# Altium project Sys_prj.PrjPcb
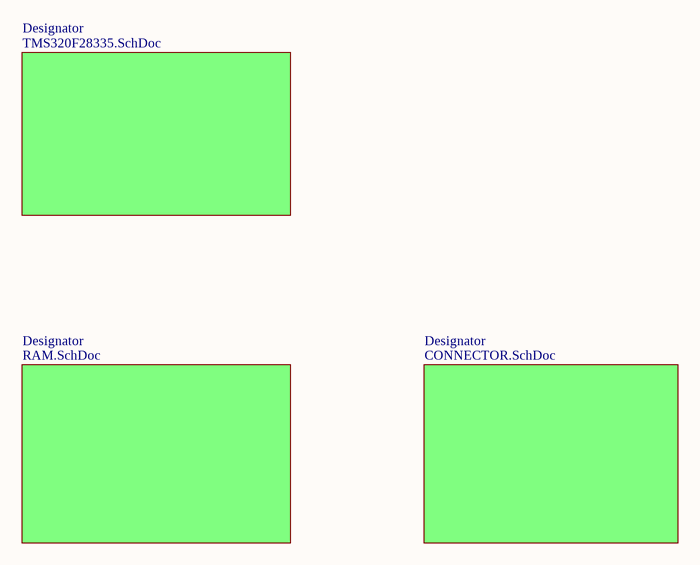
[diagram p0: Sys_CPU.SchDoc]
4 sheets, 71 parts. Net scope: global (net labels, ports and power ports of the same name join across sheets).
Board file: Sys_CPU.PcbDoc
Sheets:
  Sys_CPU.SchDoc
    Designator = TMS320F28335.SchDoc
    Designator = RAM.SchDoc
    Designator = CONNECTOR.SchDoc

## Sheet Sys_CPU.SchDoc
size A4

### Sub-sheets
Designator = TMS320F28335.SchDoc: no entries
Designator = RAM.SchDoc: no entries
Designator = CONNECTOR.SchDoc: no entries

## Sheet TMS320F28335.SchDoc
size A3
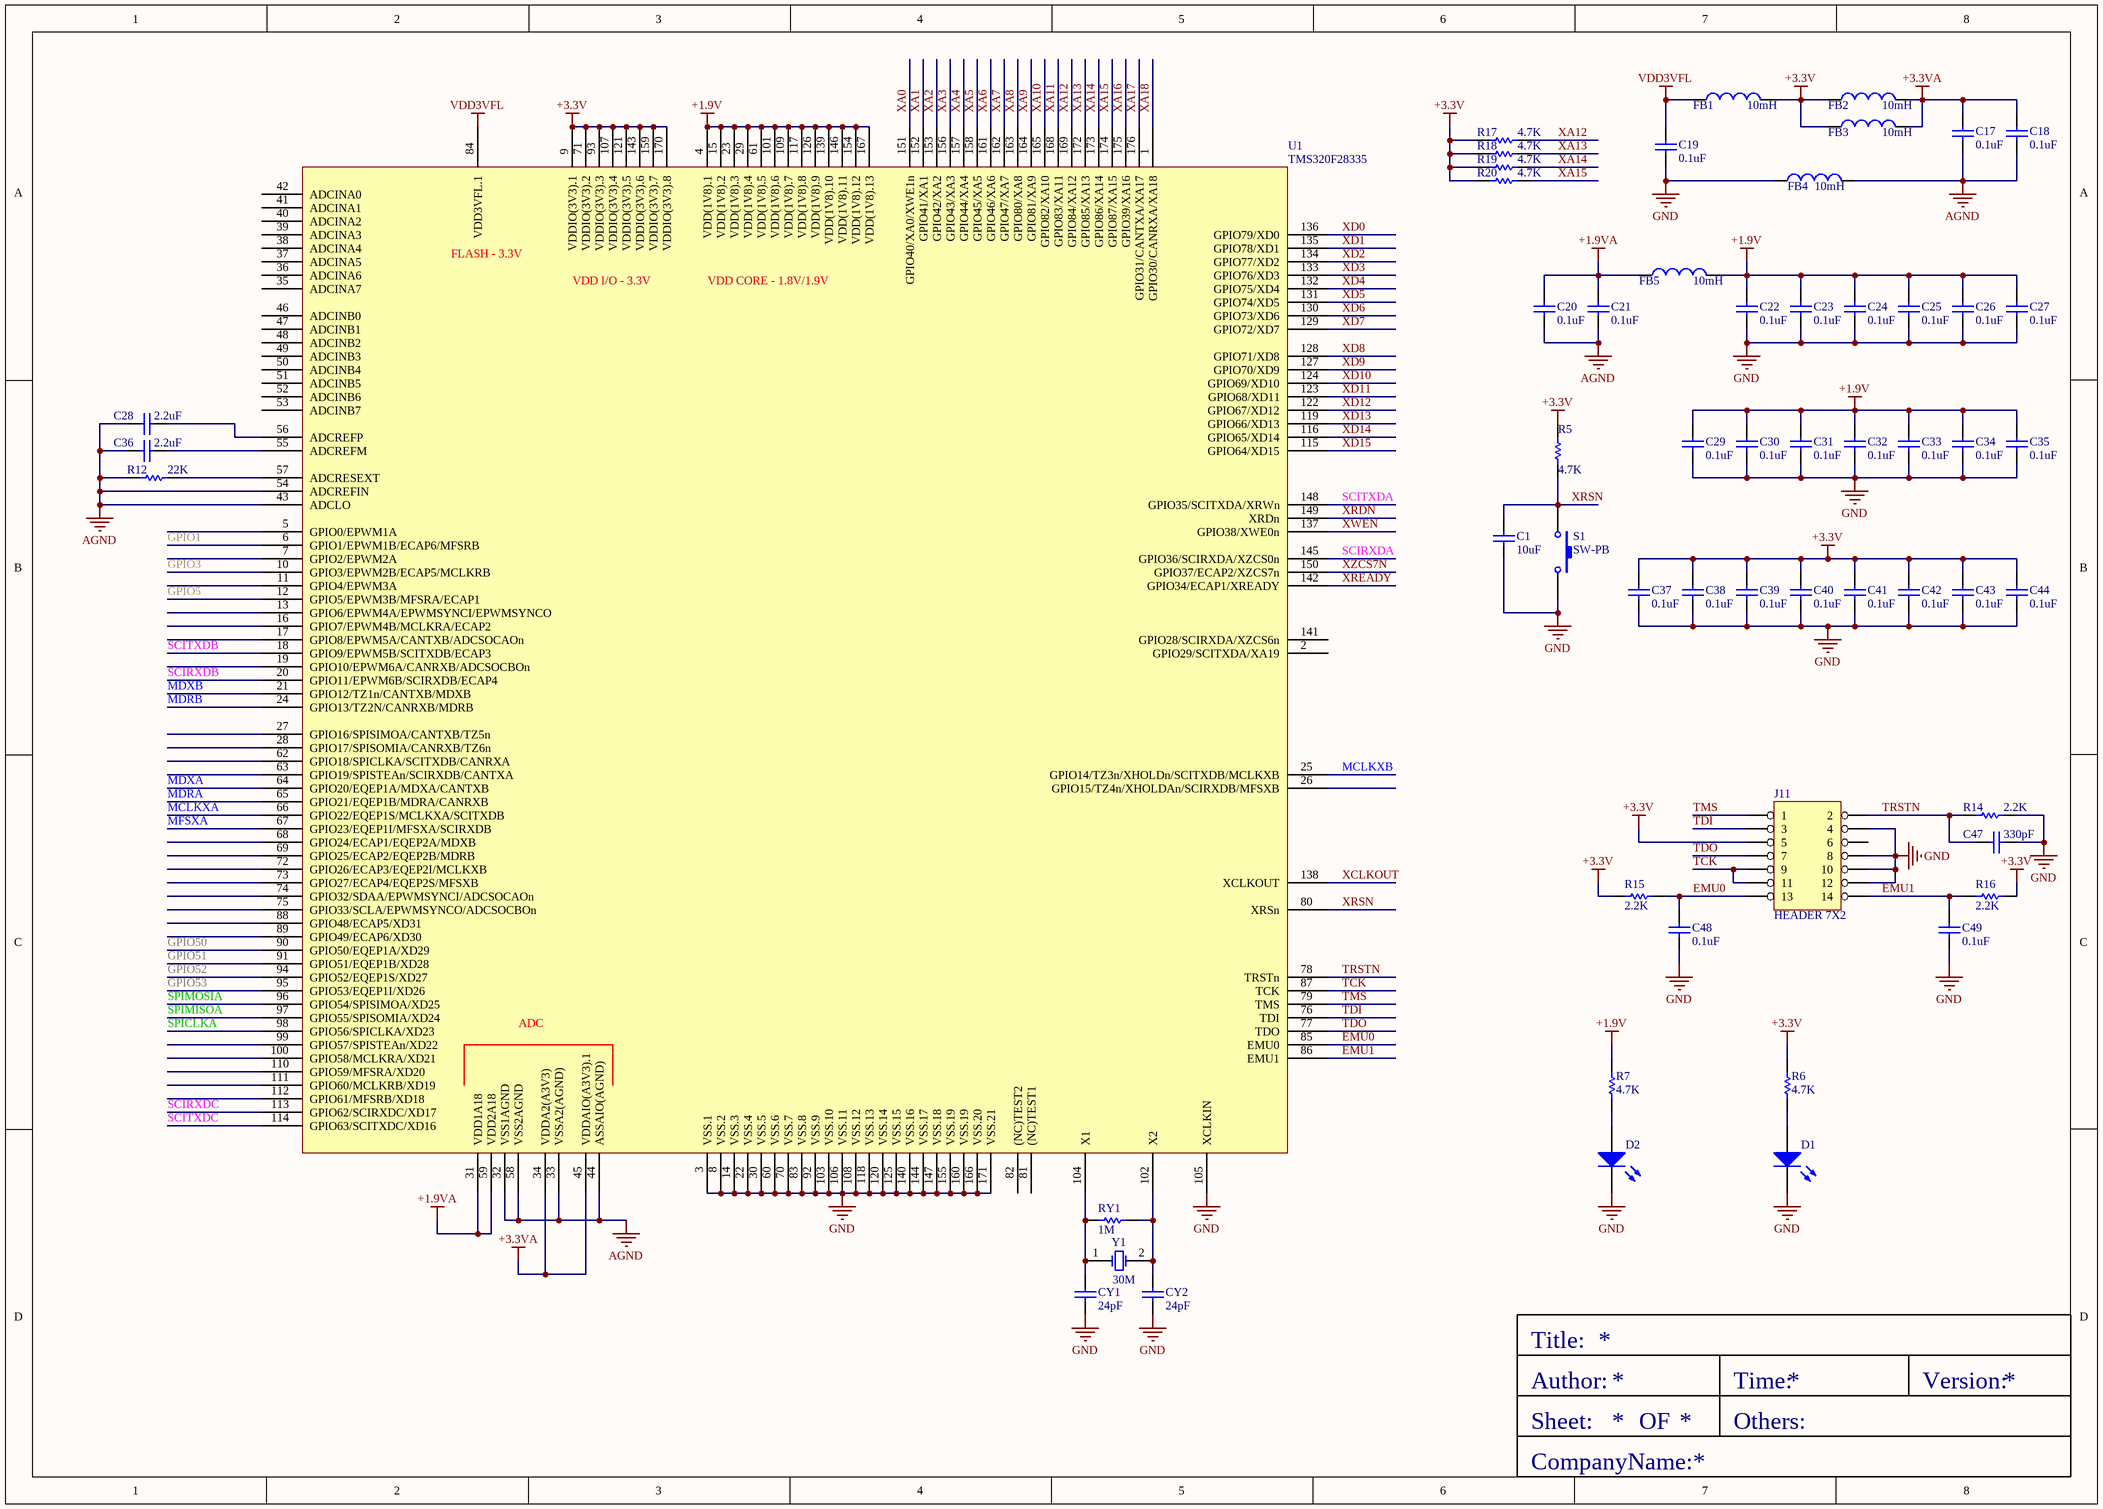
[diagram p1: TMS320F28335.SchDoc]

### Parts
C1  value 10uF  [6-0805_L]  (hidden comment: Cap)
C17  0.1uF  [1608[0603]]
C18  0.1uF  [1608[0603]]
C19  0.1uF  [1608[0603]]
C20  0.1uF  [1608[0603]]
C21  0.1uF  [1608[0603]]
C22  0.1uF  [1608[0603]]
C23  0.1uF  [1608[0603]]
C24  0.1uF  [1608[0603]]
C25  0.1uF  [1608[0603]]
C26  0.1uF  [1608[0603]]
C27  0.1uF  [1608[0603]]
C28  value 2.2uF  [6-0805_L]  (hidden comment: Cap)
C29  0.1uF  [1608[0603]]
C30  0.1uF  [1608[0603]]
C31  0.1uF  [1608[0603]]
C32  0.1uF  [1608[0603]]
C33  0.1uF  [1608[0603]]
C34  0.1uF  [1608[0603]]
C35  0.1uF  [1608[0603]]
C36  value 2.2uF  [6-0805_L]  (hidden comment: Cap)
C37  0.1uF  [1608[0603]]
C38  0.1uF  [1608[0603]]
C39  0.1uF  [1608[0603]]
C40  0.1uF  [1608[0603]]
C41  0.1uF  [1608[0603]]
C42  0.1uF  [1608[0603]]
C43  0.1uF  [1608[0603]]
C44  0.1uF  [1608[0603]]
C47  330pF  [1608[0603]]
C48  0.1uF  [1608[0603]]
C49  0.1uF  [1608[0603]]
CY1  value 24pF  [0603]  (hidden comment: Cap)
CY2  value 24pF  [0603]  (hidden comment: Cap)
D1  LED3  [SMD _LED]  (value not drawn)
D2  LED3  [SMD _LED]  (value not drawn)
FB1  value 10mH  [C1206]  (hidden comment: Inductor)
FB2  value 10mH  [C1206]  (hidden comment: Inductor)
FB3  value 10mH  [C1206]  (hidden comment: Inductor)
FB4  value 10mH  [C1206]  (hidden comment: Inductor)
FB5  value 10mH  [C1206]  (hidden comment: Inductor)
J11  HEADER 7X2  [IDC-14]
R5  value 4.7K  [1608[0603]]  (hidden comment: Res1)
R6  value 4.7K  [1608[0603]]  (hidden comment: Res1)
R7  value 4.7K  [1608[0603]]  (hidden comment: Res1)
R12  value 22K  [1608[0603]]  (hidden comment: Res1)
R14  2.2K  [1608[0603]]
R15  2.2K  [1608[0603]]
R16  2.2K  [1608[0603]]
R17  value 4.7K  [1608[0603]]  (hidden comment: Res1)
R18  value 4.7K  [1608[0603]]  (hidden comment: Res1)
R19  value 4.7K  [1608[0603]]  (hidden comment: Res1)
R20  value 4.7K  [1608[0603]]  (hidden comment: Res1)
RY1  value 1M  [0603]  (hidden comment: Res1)
S1  SW-PB  [3*6*2.5]
U1  TMS320F28335  [PQFP-176]
Y1  value 30M  [SMD-CRYSTAL-2POLE]  (hidden comment: XTAL)

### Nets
+1.9V: C22.2 C23.2 C24.2 C25.2 C26.2 C27.2 C29.2 C30.2 C31.2 C32.2 C33.2 C34.2 C35.2 FB5.2 R7.2 U1.4(VDD(1V8).1) U1.15(VDD(1V8).2) U1.23(VDD(1V8).3) U1.29(VDD(1V8).4) U1.61(VDD(1V8).5) U1.101(VDD(1V8).6) U1.109(VDD(1V8).7) U1.117(VDD(1V8).8) U1.126(VDD(1V8).9) U1.139(VDD(1V8).10) U1.146(VDD(1V8).11) U1.154(VDD(1V8).12) U1.167(VDD(1V8).13)
+1.9VA: C20.2 C21.2 FB5.1 U1.31(VDD1A18) U1.59(VDD2A18)
+3.3V: C37.2 C38.2 C39.2 C40.2 C41.2 C42.2 C43.2 C44.2 FB1.2 FB2.1 FB3.1 J11.5 R5.2 R6.2 R15.1 R16.2 R17.1 R18.1 R19.1 R20.1 U1.9(VDDIO(3V3).1) U1.71(VDDIO(3V3).2) U1.93(VDDIO(3V3).3) U1.107(VDDIO(3V3).4) U1.121(VDDIO(3V3).5) U1.143(VDDIO(3V3).6) U1.159(VDDIO(3V3).7) U1.170(VDDIO(3V3).8)
+3.3VA: C17.2 C18.2 FB2.2 FB3.2 U1.34(VDDA2(A3V3)) U1.45(VDDAIO(A3V3).1)
AGND: C17.1 C18.1 C20.1 C21.1 C28.1 C36.1 FB4.2 R12.1 U1.32(VSS1AGND) U1.33(VSSA2(AGND)) U1.43(ADCLO) U1.44(ASSAIO(AGND)) U1.54(ADCREFIN) U1.58(VSS2AGND)
GND: C1.1 C19.1 C22.1 C23.1 C24.1 C25.1 C26.1 C27.1 C29.1 C30.1 C31.1 C32.1 C33.1 C34.1 C35.1 C37.1 C38.1 C39.1 C40.1 C41.1 C42.1 C43.1 C44.1 C47.1 C48.1 C49.1 CY1.1 CY2.1 D1.2(K) D2.2(K) FB4.1 J11.4 J11.8 J11.10 J11.12 R14.2 S1.2 U1.3(VSS.1) U1.8(VSS.2) U1.14(VSS.3) U1.22(VSS.4) U1.30(VSS.5) U1.60(VSS.6) U1.70(VSS.7) U1.83(VSS.8) U1.92(VSS.9) U1.103(VSS.10) U1.105(XCLKIN) U1.106(VSS.11) U1.108(VSS.12) U1.118(VSS.13) U1.120(VSS.14) U1.125(VSS.15) U1.140(VSS.16) U1.144(VSS.17) U1.147(VSS.18) U1.155(VSS.19) U1.160(VSS.19) U1.166(VSS.20) U1.171(VSS.21)
VDD3VFL: C19.2 FB1.1 U1.84(VDD3VFL.1)
EMU0: C48.2 J11.13 R15.2 U1.85(EMU0)
EMU1: C49.2 J11.14 R16.1 U1.86(EMU1)
GPIO1: U1.6(GPIO1/EPWM1B/ECAP6/MFSRB)
GPIO3: U1.10(GPIO3/EPWM2B/ECAP5/MCLKRB)
GPIO5: U1.12(GPIO5/EPWM3B/MFSRA/ECAP1)
GPIO50: U1.90(GPIO50/EQEP1A/XD29)
GPIO51: U1.91(GPIO51/EQEP1B/XD28)
GPIO52: U1.94(GPIO52/EQEP1S/XD27)
GPIO53: U1.95(GPIO53/EQEP1I/XD26)
MCLKXA: U1.66(GPIO22/EQEP1S/MCLKXA/SCITXDB)
MCLKXB: U1.25(GPIO14/TZ3n/XHOLDn/SCITXDB/MCLKXB)
MDRA: U1.65(GPIO21/EQEP1B/MDRA/CANRXB)
MDRB: U1.24(GPIO13/TZ2N/CANRXB/MDRB)
MDXA: U1.64(GPIO20/EQEP1A/MDXA/CANTXB)
MDXB: U1.21(GPIO12/TZ1n/CANTXB/MDXB)
MFSXA: U1.67(GPIO23/EQEP1I/MFSXA/SCIRXDB)
SCIRXDA: U1.145(GPIO36/SCIRXDA/XZCS0n)
SCIRXDB: U1.20(GPIO11/EPWM6B/SCIRXDB/ECAP4)
SCIRXDC: U1.113(GPIO62/SCIRXDC/XD17)
SCITXDA: U1.148(GPIO35/SCITXDA/XRWn)
SCITXDB: U1.18(GPIO9/EPWM5B/SCITXDB/ECAP3)
SCITXDC: U1.114(GPIO63/SCITXDC/XD16)
SPICLKA: U1.98(GPIO56/SPICLKA/XD23)
SPIMISOA: U1.97(GPIO55/SPISOMIA/XD24)
SPIMOSIA: U1.96(GPIO54/SPISIMOA/XD25)
TCK: J11.9 J11.11 U1.87(TCK)
TDI: J11.3 U1.76(TDI)
TDO: J11.7 U1.77(TDO)
TMS: J11.1 U1.79(TMS)
TRSTN: C47.2 J11.2 R14.1 U1.78(TRSTn)
XA0: U1.151(GPIO40/XA0/XWE1n)
XA1: U1.152(GPIO41/XA1)
XA2: U1.153(GPIO42/XA2)
XA3: U1.156(GPIO43/XA3)
XA4: U1.157(GPIO44/XA4)
XA5: U1.158(GPIO45/XA5)
XA6: U1.161(GPIO46/XA6)
XA7: U1.162(GPIO47/XA7)
XA8: U1.163(GPIO80/XA8)
XA9: U1.164(GPIO81/XA9)
XA10: U1.165(GPIO82/XA10)
XA11: U1.168(GPIO83/XA11)
XA12: R17.2 U1.169(GPIO84/XA12)
XA13: R18.2 U1.172(GPIO85/XA13)
XA14: R19.2 U1.173(GPIO86/XA14)
XA15: R20.2 U1.174(GPIO87/XA15)
XA16: U1.175(GPIO39/XA16)
XA17: U1.176(GPIO31/CANTXA/XA17)
XA18: U1.1(GPIO30/CANRXA/XA18)
XCLKOUT: U1.138(XCLKOUT)
XD0: U1.136(GPIO79/XD0)
XD1: U1.135(GPIO78/XD1)
XD2: U1.134(GPIO77/XD2)
XD3: U1.133(GPIO76/XD3)
XD4: U1.132(GPIO75/XD4)
XD5: U1.131(GPIO74/XD5)
XD6: U1.130(GPIO73/XD6)
XD7: U1.129(GPIO72/XD7)
XD8: U1.128(GPIO71/XD8)
XD9: U1.127(GPIO70/XD9)
XD10: U1.124(GPIO69/XD10)
XD11: U1.123(GPIO68/XD11)
XD12: U1.122(GPIO67/XD12)
XD13: U1.119(GPIO66/XD13)
XD14: U1.116(GPIO65/XD14)
XD15: U1.115(GPIO64/XD15)
XRDN: U1.149(XRDn)
XREADY: U1.142(GPIO34/ECAP1/XREADY)
XRSN: C1.2 R5.1 S1.1 U1.80(XRSn)
XWEN: U1.137(GPIO38/XWE0n)
XZCS7N: U1.150(GPIO37/ECAP2/XZCS7n)
NetC28_2: C28.2 U1.56(ADCREFP)
NetC36_2: C36.2 U1.55(ADCREFM)
NetCY1_2: CY1.2 RY1.2 U1.104(X1) Y1.1(OSC1)
NetCY2_2: CY2.2 RY1.1 U1.102(X2) Y1.2(OSC2)
NetD1_1: D1.1(A) R6.1
NetD2_1: D2.1(A) R7.1
NetR12_2: R12.2 U1.57(ADCRESEXT)

Not connected (* = marked no-connect by the designer): J11 6; U1 2(GPIO29/SCITXDA/XA19) 5(GPIO0/EPWM1A) 7(GPIO2/EPWM2A) 11(GPIO4/EPWM3A) 13(GPIO6/EPWM4A/EPWMSYNCI/EPWMSYNCO) 16(GPIO7/EPWM4B/MCLKRA/ECAP2) 17(GPIO8/EPWM5A/CANTXB/ADCSOCAOn) 19(GPIO10/EPWM6A/CANRXB/ADCSOCBOn) 26(GPIO15/TZ4n/XHOLDAn/SCIRXDB/MFSXB) 27(GPIO16/SPISIMOA/CANTXB/TZ5n) 28(GPIO17/SPISOMIA/CANRXB/TZ6n) 35(ADCINA7) 36(ADCINA6) 37(ADCINA5) 38(ADCINA4) 39(ADCINA3) 40(ADCINA2) 41(ADCINA1) 42(ADCINA0) 46(ADCINB0) 47(ADCINB1) 48(ADCINB2) 49(ADCINB3) 50(ADCINB4) 51(ADCINB5) 52(ADCINB6) 53(ADCINB7) 62(GPIO18/SPICLKA/SCITXDB/CANRXA) 63(GPIO19/SPISTEAn/SCIRXDB/CANTXA) 68(GPIO24/ECAP1/EQEP2A/MDXB) 69(GPIO25/ECAP2/EQEP2B/MDRB) 72(GPIO26/ECAP3/EQEP2I/MCLKXB) 73(GPIO27/ECAP4/EQEP2S/MFSXB) 74(GPIO32/SDAA/EPWMSYNCI/ADCSOCAOn) 75(GPIO33/SCLA/EPWMSYNCO/ADCSOCBOn) 81((NC)TEST1) 82((NC)TEST2) 88(GPIO48/ECAP5/XD31) 89(GPIO49/ECAP6/XD30) 99(GPIO57/SPISTEAn/XD22) 100(GPIO58/MCLKRA/XD21) 110(GPIO59/MFSRA/XD20) 111(GPIO60/MCLKRB/XD19) 112(GPIO61/MFSRB/XD18) 141(GPIO28/SCIRXDA/XZCS6n)

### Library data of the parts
C1 C28 C36 CY1 CY2 = Cap: Capacitor
C17-C27 C29-C35 C37-C44 C47-C49 = Cap: Capacitor; Value: 100pF
D1 D2 = LED3: Typical BLUE SiC LED
FB1-FB5 = Inductor: Code_IEC: 1005
R5-R7 R12 R17-R20 RY1 = Res1: Resistor
R14-R16 = Res1: Resistor; Value: 1K
S1 = SW-PB: Switch
Y1 = XTAL: Crystal Oscillator

## Sheet RAM.SchDoc
size A4
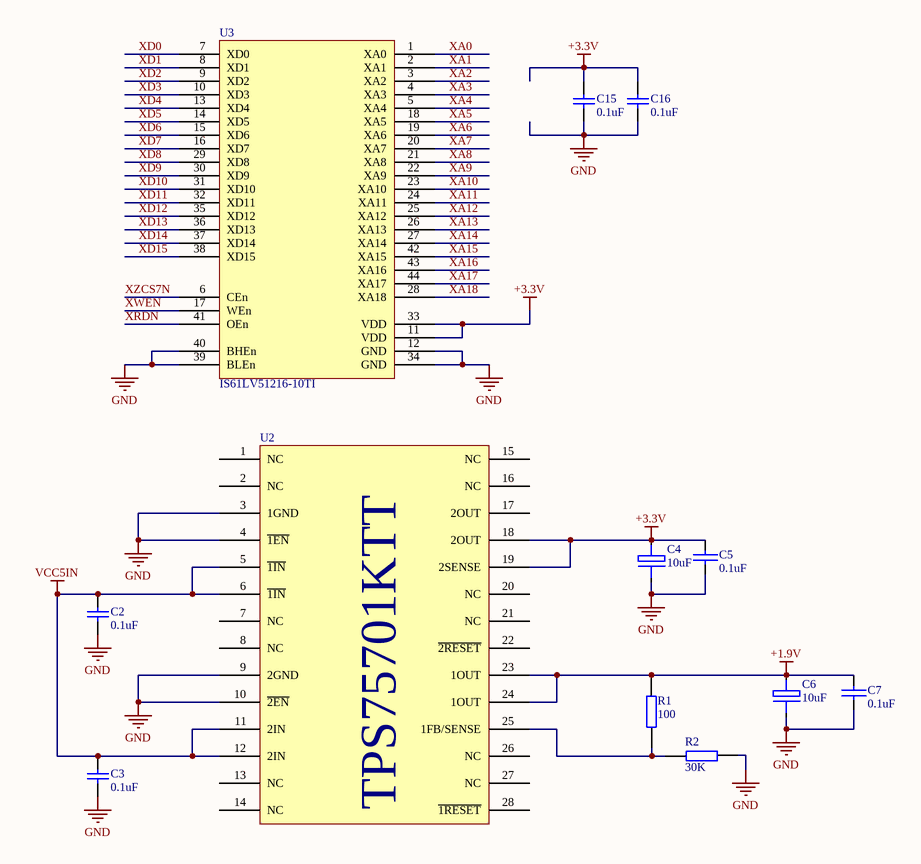
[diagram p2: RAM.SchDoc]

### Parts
C2  0.1uF  [1608[0603]]
C3  value 0.1uF  [1608[0603]]  (hidden comment: Cap)
C4  10uF  [1206]
C5  0.1uF  [0603]
C6  10uF  [1206]
C7  0.1uF  [0603]
C15  value 0.1uF  [1608[0603]]  (hidden comment: Cap)
C16  value 0.1uF  [1608[0603]]  (hidden comment: Cap)
R1  100  [0805]
R2  30K  [0805]
U2  TPS75701KTT  [TPS301]
U3  IS61LV51216-10TI  [TSOP-44]

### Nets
+1.9V: C6.1 C7.1 R1.1 U2.23(1OUT) U2.24(1OUT)
+3.3V: C4.1 C5.1 C15.2 C16.2 U2.18(2OUT) U2.19(2SENSE) U3.11(VDD) U3.33(VDD)
GND: C2.1 C3.1 C4.2 C5.2 C6.2 C7.2 C15.1 C16.1 R2.2 U2.3(1GND) U2.4(~{1EN}) U2.9(2GND) U2.10(~{2EN}) U3.12(GND) U3.34(GND) U3.39(BLEn) U3.40(BHEn)
VCC5IN: C2.2 C3.2 U2.5(~{1IN}) U2.6(~{1IN}) U2.11(2IN) U2.12(2IN)
XA0: U3.1(XA0)
XA1: U3.2(XA1)
XA2: U3.3(XA2)
XA3: U3.4(XA3)
XA4: U3.5(XA4)
XA5: U3.18(XA5)
XA6: U3.19(XA6)
XA7: U3.20(XA7)
XA8: U3.21(XA8)
XA9: U3.22(XA9)
XA10: U3.23(XA10)
XA11: U3.24(XA11)
XA12: U3.25(XA12)
XA13: U3.26(XA13)
XA14: U3.27(XA14)
XA15: U3.42(XA15)
XA16: U3.43(XA16)
XA17: U3.44(XA17)
XA18: U3.28(XA18)
XD0: U3.7(XD0)
XD1: U3.8(XD1)
XD2: U3.9(XD2)
XD3: U3.10(XD3)
XD4: U3.13(XD4)
XD5: U3.14(XD5)
XD6: U3.15(XD6)
XD7: U3.16(XD7)
XD8: U3.29(XD8)
XD9: U3.30(XD9)
XD10: U3.31(XD10)
XD11: U3.32(XD11)
XD12: U3.35(XD12)
XD13: U3.36(XD13)
XD14: U3.37(XD14)
XD15: U3.38(XD15)
XRDN: U3.41(OEn)
XWEN: U3.17(WEn)
XZCS7N: U3.6(CEn)
NetR1_2: R1.2 R2.1 U2.25(1FB/SENSE)

Not connected (* = marked no-connect by the designer): U2 1(NC) 2(NC) 7(NC) 8(NC) 13(NC) 14(NC) 15(NC) 16(NC) 17(2OUT) 20(NC) 21(NC) 22(~{2RESET}) 26(NC) 27(NC) 28(~{1RESET})

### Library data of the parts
C2 C3 C15 C16 = Cap: Capacitor
C4 C6 = C
C5 C7 = C1
R1 R2 = R
U2 = tps301
U3 = Component_1_1

## Sheet CONNECTOR.SchDoc
size A4
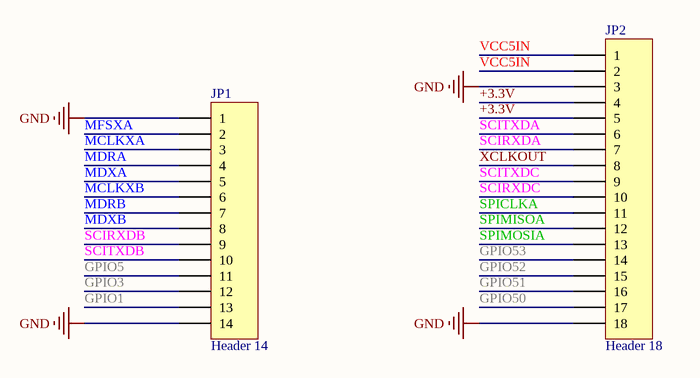
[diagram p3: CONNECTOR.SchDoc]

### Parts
JP1  Header 14  [HDR1X14]
JP2  Header 18  [HDR1X18]

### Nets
+3.3V: JP2.4 JP2.5
GND: JP1.1 JP1.14 JP2.3 JP2.18
VCC5IN: JP2.1 JP2.2
GPIO1: JP1.13
GPIO3: JP1.12
GPIO5: JP1.11
GPIO50: JP2.17
GPIO51: JP2.16
GPIO52: JP2.15
GPIO53: JP2.14
MCLKXA: JP1.3
MCLKXB: JP1.6
MDRA: JP1.4
MDRB: JP1.7
MDXA: JP1.5
MDXB: JP1.8
MFSXA: JP1.2
SCIRXDA: JP2.7
SCIRXDB: JP1.9
SCIRXDC: JP2.10
SCITXDA: JP2.6
SCITXDB: JP1.10
SCITXDC: JP2.9
SPICLKA: JP2.11
SPIMISOA: JP2.12
SPIMOSIA: JP2.13
XCLKOUT: JP2.8

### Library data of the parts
JP1 = Header 14: Header, 14-Pin
JP2 = Header 18: Header, 18-Pin

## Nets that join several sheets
+1.9V: TMS320F28335 (28 pins), RAM (5 pins)
+3.3V: TMS320F28335 (28 pins), RAM (8 pins), CONNECTOR (JP2.4 JP2.5)
GND: TMS320F28335 (60 pins), RAM (17 pins), CONNECTOR (JP1.1 JP1.14 JP2.3 JP2.18)
VCC5IN: RAM (6 pins), CONNECTOR (JP2.1 JP2.2)
GPIO1: TMS320F28335 (U1.6), CONNECTOR (JP1.13)
GPIO3: TMS320F28335 (U1.10), CONNECTOR (JP1.12)
GPIO5: TMS320F28335 (U1.12), CONNECTOR (JP1.11)
GPIO50: TMS320F28335 (U1.90), CONNECTOR (JP2.17)
GPIO51: TMS320F28335 (U1.91), CONNECTOR (JP2.16)
GPIO52: TMS320F28335 (U1.94), CONNECTOR (JP2.15)
GPIO53: TMS320F28335 (U1.95), CONNECTOR (JP2.14)
MCLKXA: TMS320F28335 (U1.66), CONNECTOR (JP1.3)
MCLKXB: TMS320F28335 (U1.25), CONNECTOR (JP1.6)
MDRA: TMS320F28335 (U1.65), CONNECTOR (JP1.4)
MDRB: TMS320F28335 (U1.24), CONNECTOR (JP1.7)
MDXA: TMS320F28335 (U1.64), CONNECTOR (JP1.5)
MDXB: TMS320F28335 (U1.21), CONNECTOR (JP1.8)
MFSXA: TMS320F28335 (U1.67), CONNECTOR (JP1.2)
SCIRXDA: TMS320F28335 (U1.145), CONNECTOR (JP2.7)
SCIRXDB: TMS320F28335 (U1.20), CONNECTOR (JP1.9)
SCIRXDC: TMS320F28335 (U1.113), CONNECTOR (JP2.10)
SCITXDA: TMS320F28335 (U1.148), CONNECTOR (JP2.6)
SCITXDB: TMS320F28335 (U1.18), CONNECTOR (JP1.10)
SCITXDC: TMS320F28335 (U1.114), CONNECTOR (JP2.9)
SPICLKA: TMS320F28335 (U1.98), CONNECTOR (JP2.11)
SPIMISOA: TMS320F28335 (U1.97), CONNECTOR (JP2.12)
SPIMOSIA: TMS320F28335 (U1.96), CONNECTOR (JP2.13)
XA0: TMS320F28335 (U1.151), RAM (U3.1)
XA1: TMS320F28335 (U1.152), RAM (U3.2)
XA2: TMS320F28335 (U1.153), RAM (U3.3)
XA3: TMS320F28335 (U1.156), RAM (U3.4)
XA4: TMS320F28335 (U1.157), RAM (U3.5)
XA5: TMS320F28335 (U1.158), RAM (U3.18)
XA6: TMS320F28335 (U1.161), RAM (U3.19)
XA7: TMS320F28335 (U1.162), RAM (U3.20)
XA8: TMS320F28335 (U1.163), RAM (U3.21)
XA9: TMS320F28335 (U1.164), RAM (U3.22)
XA10: TMS320F28335 (U1.165), RAM (U3.23)
XA11: TMS320F28335 (U1.168), RAM (U3.24)
XA12: TMS320F28335 (R17.2 U1.169), RAM (U3.25)
XA13: TMS320F28335 (R18.2 U1.172), RAM (U3.26)
XA14: TMS320F28335 (R19.2 U1.173), RAM (U3.27)
XA15: TMS320F28335 (R20.2 U1.174), RAM (U3.42)
XA16: TMS320F28335 (U1.175), RAM (U3.43)
XA17: TMS320F28335 (U1.176), RAM (U3.44)
XA18: TMS320F28335 (U1.1), RAM (U3.28)
XCLKOUT: TMS320F28335 (U1.138), CONNECTOR (JP2.8)
XD0: TMS320F28335 (U1.136), RAM (U3.7)
XD1: TMS320F28335 (U1.135), RAM (U3.8)
XD2: TMS320F28335 (U1.134), RAM (U3.9)
XD3: TMS320F28335 (U1.133), RAM (U3.10)
XD4: TMS320F28335 (U1.132), RAM (U3.13)
XD5: TMS320F28335 (U1.131), RAM (U3.14)
XD6: TMS320F28335 (U1.130), RAM (U3.15)
XD7: TMS320F28335 (U1.129), RAM (U3.16)
XD8: TMS320F28335 (U1.128), RAM (U3.29)
XD9: TMS320F28335 (U1.127), RAM (U3.30)
XD10: TMS320F28335 (U1.124), RAM (U3.31)
XD11: TMS320F28335 (U1.123), RAM (U3.32)
XD12: TMS320F28335 (U1.122), RAM (U3.35)
XD13: TMS320F28335 (U1.119), RAM (U3.36)
XD14: TMS320F28335 (U1.116), RAM (U3.37)
XD15: TMS320F28335 (U1.115), RAM (U3.38)
XRDN: TMS320F28335 (U1.149), RAM (U3.41)
XWEN: TMS320F28335 (U1.137), RAM (U3.17)
XZCS7N: TMS320F28335 (U1.150), RAM (U3.6)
